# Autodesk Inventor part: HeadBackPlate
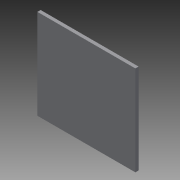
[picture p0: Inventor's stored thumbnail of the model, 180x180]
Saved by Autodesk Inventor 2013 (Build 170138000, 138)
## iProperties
Created: 2013-04
Part Number: HeadBackPlate
Material: Generic
Document SubType Name: Modeling
Designer: frankenteddy
Density: 1 g/cm^3
Author: frankenteddy
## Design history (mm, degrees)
sketch "Sketch1"
  geometry: L1 (-24.5, 22.5)-(24.5, 22.5); L2 (24.5, 22.5)-(24.5, -22.5); L3 (24.5, -22.5)-(-24.5, -22.5); L4 (-24.5, -22.5)-(-24.5, 22.5); 3 further points
  constraints: 8 end point, 2 midpoint, 2 parallel, 1 horizontal, 1 horizontal alignment, 1 perpendicular, 1 vertical alignment
  dimensions: "d0" = 49 distance of L2.end L3.end; "d1" = 45 distance of L1.end L2.end
extrude "Extrusion1" new body sketch "Sketch1" distance "d2" = 1.62; taper "d3" = 0 deg
sketch "Sketch2"
  geometry: L1 (-24.5, -22.5)-(24.5, -22.5) reference; L2 (24.5, -22.5)-(24.5, 22.5) reference; L3 (24.5, 22.5)-(-24.5, 22.5) reference; L4 (-24.5, 22.5)-(-24.5, -22.5) reference; L5 (-24.5, 0)-(24.5, 0); L6 (0, 22.5)-(0, -22.5); L7 (0, 5.295)-(4.585, 2.647); L8 (4.585, 2.647)-(4.585, -2.647); L9 (4.585, -2.647)-(0, -5.295); L10 (0, -5.295)-(-4.585, -2.647); L11 (-4.585, -2.647)-(-4.585, 2.647); L12 (-4.585, 2.647)-(0, 5.295); L13 (11.786, 0.682)-(14.34, -1.554); L14 (14.34, -1.554)-(13.681, -4.883); L15 (13.681, -4.883)-(10.468, -5.977); L16 (10.468, -5.977)-(7.915, -3.741); L17 (7.915, -3.741)-(8.574, -0.412); L18 (8.574, -0.412)-(11.786, 0.682); L19 (17.608, -8.105)-(18.025, -10.918); L20 (18.025, -10.918)-(15.797, -12.686); L21 (15.797, -12.686)-(13.152, -11.641); L22 (13.152, -11.641)-(12.735, -8.828); L23 (12.735, -8.828)-(14.963, -7.06); L24 (14.963, -7.06)-(17.608, -8.105); L25 (10.468, -18.433)-(7.259, -18.054); L26 (7.259, -18.054)-(5.982, -15.086); L27 (5.982, -15.086)-(7.915, -12.495); L28 (7.915, -12.495)-(11.124, -12.874); L29 (11.124, -12.874)-(12.401, -15.843); L30 (12.401, -15.843)-(10.468, -18.433); L31 (-3.371, -18.433)-(-4.626, -15.426); L32 (-4.626, -15.426)-(-2.649, -12.836); L33 (-2.649, -12.836)-(0.583, -13.253); L34 (0.583, -13.253)-(1.838, -16.26); L35 (1.838, -16.26)-(-0.139, -18.85); L36 (-0.139, -18.85)-(-3.371, -18.433); L37 (-15.124, -14.756)-(-15.249, -11.133); L38 (-15.249, -11.133)-(-12.174, -9.212); L39 (-12.174, -9.212)-(-8.973, -10.915); L40 (-8.973, -10.915)-(-8.847, -14.539); L41 (-8.847, -14.539)-(-11.923, -16.459); L42 (-11.923, -16.459)-(-15.124, -14.756); L43 (-21.055, -5.977)-(-21.327, -1.978); L44 (-21.327, -1.978)-(-18.001, 0.257); L45 (-18.001, 0.257)-(-14.401, -1.506); L46 (-14.401, -1.506)-(-14.129, -5.505); L47 (-14.129, -5.505)-(-17.456, -7.74); L48 (-17.456, -7.74)-(-21.055, -5.977); L49 (-18.638, 10.567)-(-13.981, 11.165); L50 (-13.981, 11.165)-(-11.135, 7.43); L51 (-11.135, 7.43)-(-12.946, 3.098); L52 (-12.946, 3.098)-(-17.603, 2.5); L53 (-17.603, 2.5)-(-20.45, 6.235); L54 (-20.45, 6.235)-(-18.638, 10.567); L55 (-8.847, 18.94)-(-4.139, 17.132); L56 (-4.139, 17.132)-(-3.35, 12.15); L57 (-3.35, 12.15)-(-7.271, 8.977); L58 (-7.271, 8.977)-(-11.979, 10.785); L59 (-11.979, 10.785)-(-12.767, 15.767); L60 (-12.767, 15.767)-(-8.847, 18.94); L61 (2.293, 17.353)-(3.92, 14.747); L62 (3.92, 14.747)-(2.476, 12.035); L63 (2.476, 12.035)-(-0.595, 11.929); L64 (-0.595, 11.929)-(-2.222, 14.535)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; 14 further points
  constraints: 160 end point, 4 midpoint, 1 coincident, 1 point on line, 169 other
extrude "Extrusion2" join sketch "Sketch2" distance "d4" = 2; taper "d5" = 0 deg
body "Solid1"
